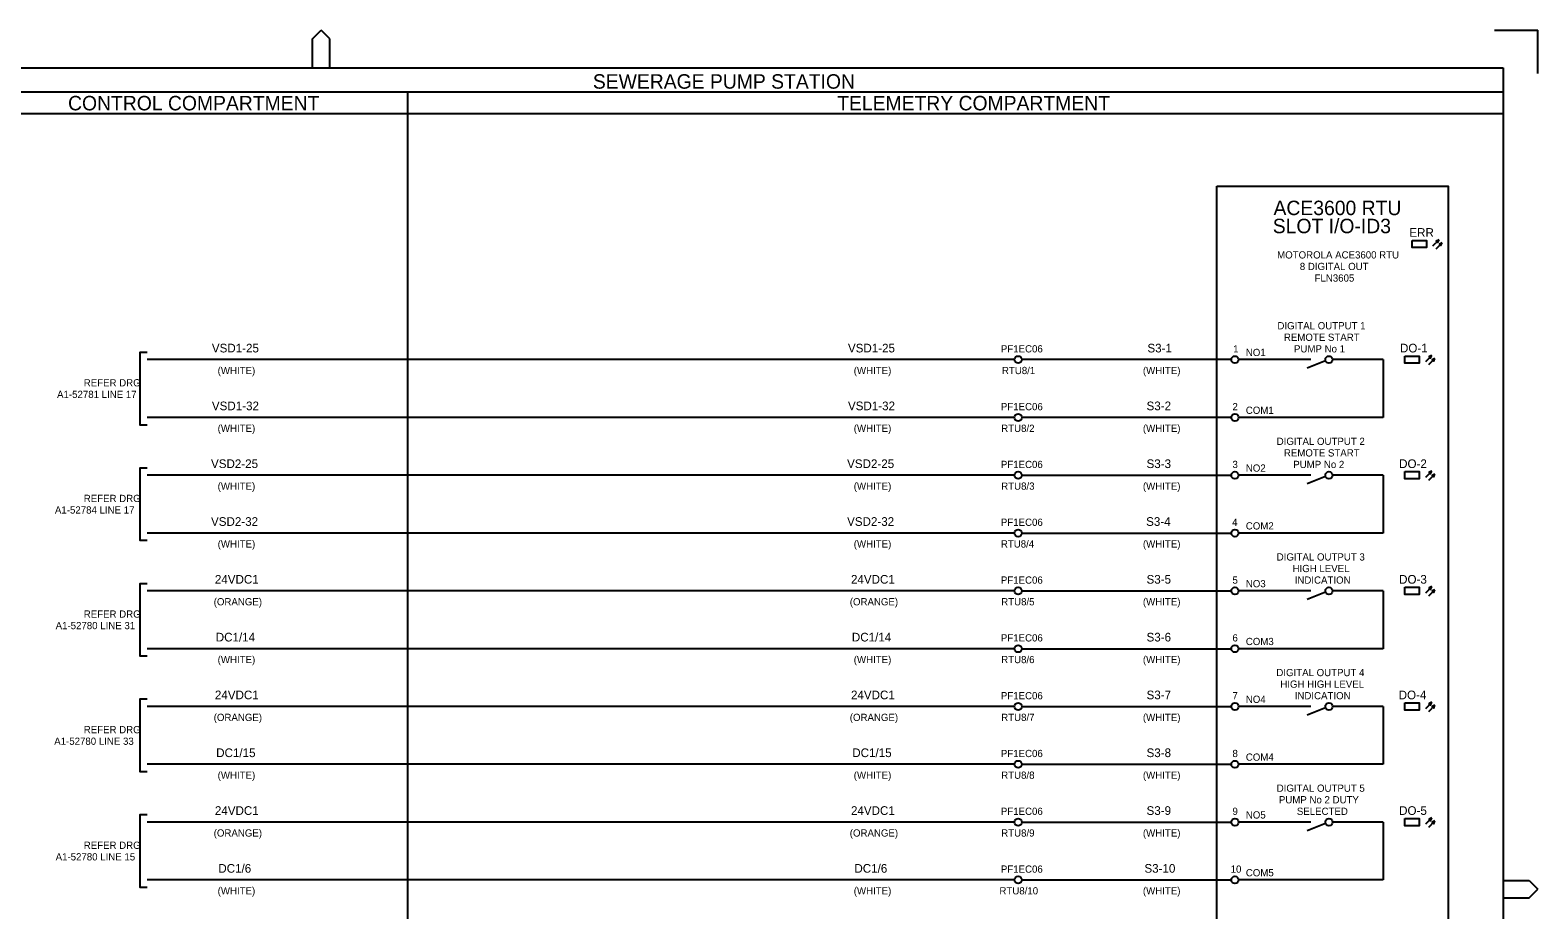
# Model space of a CAD drawing. Extents: x 0 to 841, y 0 to 594.
# Drawn here: x 320 to 841, y 290 to 594 of the extents above; entities that cross this region are included whole.
import ezdxf

# ---------------------------------------------------------------- set-up
doc = ezdxf.new("R2010")
doc.units = 0
for name, color, linetype in [('A1BORDER', 7, 'Continuous'), ('Level 1', 7, 'Continuous'), ('Level 10', 7, 'Continuous')]:
    doc.layers.add(name, color=color, linetype=linetype)

msp = doc.modelspace()

# ---------------------------------------------------------------- linework, layer by layer
at = {"layer": 'A1BORDER'}
for p, q in [((417.19, 591), (420.19, 594)), ((417.19, 581), (417.19, 591)), ((423.19, 591), (420.19, 594)), ((423.19, 581), (423.19, 591)), ((826, 594), (841, 594)), ((841, 579), (841, 594)), ((28, 581), (829, 581)), ((829, 581), (829, 15)), ((829, 299.76), (838, 299.76)), ((838, 299.76), (841, 296.76)), ((829, 293.76), (838, 293.76)), ((838, 293.76), (841, 296.76))]:
    msp.add_line(p, q, dxfattribs=at)
at = {"layer": 'Level 1'}
for p, q in [((829, 572.5), (160, 572.5)), ((450, 572.5), (450, 57)), ((829, 565), (160, 565)), ((660, 480), (360, 480)), ((735, 480), (662.5, 480)), ((760, 480), (737.5, 480)), ((762.5, 480), (760, 480)), ((787.5, 480), (770, 480)), ((787.5, 480), (787.5, 460)), ((660, 460), (360, 460)), ((735, 460), (662.5, 460)), ((787.5, 460), (737.5, 460)), ((660, 440), (360, 440)), ((662.5, 440), (735, 440)), ((760, 440), (737.5, 440)), ((762.5, 440), (760, 440)), ((787.5, 440), (770, 440)), ((787.5, 440), (787.5, 420)), ((660, 420), (360, 420)), ((662.5, 420), (735, 420)), ((787.5, 420), (737.5, 420)), ((660, 400), (360, 400)), ((662.5, 400), (735, 400)), ((760, 400), (737.5, 400)), ((762.5, 400), (760, 400)), ((787.5, 400), (770, 400)), ((787.5, 400), (787.5, 380)), ((660, 380), (360, 380)), ((662.5, 380), (735, 380)), ((787.5, 380), (737.5, 380)), ((660, 360), (360, 360)), ((662.5, 360), (735, 360)), ((760, 360), (737.5, 360)), ((762.5, 360), (760, 360)), ((787.5, 360), (770, 360)), ((787.5, 360), (787.5, 340)), ((660, 340), (360, 340)), ((662.5, 340), (735, 340)), ((787.5, 340), (737.5, 340)), ((660, 320), (360, 320)), ((662.5, 320), (735, 320)), ((760, 320), (737.5, 320)), ((762.5, 320), (760, 320)), ((787.5, 320), (770, 320)), ((787.5, 320), (787.5, 300)), ((660, 300), (360, 300)), ((662.5, 300), (735, 300)), ((787.5, 300), (737.5, 300))]:
    msp.add_line(p, q, dxfattribs=at)
for points in [[(730, 540), (810, 540), (810, 80), (730, 80)], [(797.5, 521.25), (802.5, 521.25), (802.5, 518.75), (797.5, 518.75)], [(795, 481.25), (800, 481.25), (800, 478.75), (795, 478.75)], [(795, 441.25), (800, 441.25), (800, 438.75), (795, 438.75)], [(795, 401.25), (800, 401.25), (800, 398.75), (795, 398.75)], [(795, 361.25), (800, 361.25), (800, 358.75), (795, 358.75)], [(795, 321.25), (800, 321.25), (800, 318.75), (795, 318.75)]]:
    msp.add_lwpolyline(points, close=True, dxfattribs=at)
for points in [[(360, 482.5), (357.5, 482.5), (357.5, 457.5), (360, 457.5)], [(360, 442.5), (357.5, 442.5), (357.5, 417.5), (360, 417.5)], [(360, 402.5), (357.5, 402.5), (357.5, 377.5), (360, 377.5)], [(360, 362.5), (357.5, 362.5), (357.5, 337.5), (360, 337.5)], [(360, 322.5), (357.5, 322.5), (357.5, 297.5), (360, 297.5)]]:
    msp.add_lwpolyline(points, dxfattribs=at)
for centre in [(661.25, 480), (736.25, 480), (661.25, 460), (736.25, 460), (661.25, 440), (736.25, 440), (661.25, 420), (736.25, 420), (661.25, 400), (736.25, 400), (661.25, 380), (736.25, 380), (661.25, 360), (736.25, 360), (661.25, 340), (736.25, 340), (661.25, 320), (736.25, 320), (661.25, 300), (736.25, 300)]:
    msp.add_circle(centre, 1.25, dxfattribs=at)
at = {"layer": 'Level 10'}
for p, q in [((804.73, 519.36), (806.86, 521.48)), ((805.79, 518.29), (807.91, 520.42)), ((805.96, 521.08), (806.67, 521.08)), ((806, 520.92), (806.61, 520.92)), ((806.14, 520.77), (806.53, 520.77)), ((806.29, 521.23), (806.74, 521.23)), ((806.3, 520.62), (806.47, 520.62)), ((806.62, 521.38), (806.81, 521.38)), ((807.02, 520.01), (807.73, 520.01)), ((807.06, 519.87), (807.66, 519.87)), ((807.21, 519.72), (807.6, 519.72)), ((807.35, 520.16), (807.8, 520.16)), ((807.36, 519.57), (807.53, 519.57)), ((807.68, 520.32), (807.87, 520.32)), ((802.23, 479.36), (804.36, 481.48)), ((803.29, 478.3), (805.41, 480.42)), ((803.46, 481.07), (804.17, 481.07)), ((803.5, 480.93), (804.11, 480.93)), ((803.64, 480.78), (804.03, 480.78)), ((803.79, 481.23), (804.24, 481.23)), ((803.8, 480.62), (803.97, 480.62)), ((804.12, 481.38), (804.31, 481.38)), ((804.52, 480.01), (805.23, 480.01)), ((804.56, 479.87), (805.16, 479.87)), ((804.85, 480.17), (805.3, 480.17)), ((805.18, 480.31), (805.37, 480.31)), ((767.59, 479.54), (761.25, 477)), ((804.71, 479.72), (805.1, 479.72)), ((804.86, 479.56), (805.03, 479.56)), ((767.59, 439.54), (761.25, 437)), ((802.23, 439.36), (804.36, 441.48)), ((803.29, 438.3), (805.41, 440.42)), ((803.46, 441.07), (804.17, 441.07)), ((803.5, 440.93), (804.11, 440.93)), ((803.64, 440.78), (804.03, 440.78)), ((803.79, 441.23), (804.24, 441.23)), ((803.8, 440.62), (803.97, 440.62)), ((804.12, 441.38), (804.31, 441.38)), ((804.52, 440.01), (805.23, 440.01)), ((804.56, 439.87), (805.16, 439.87)), ((804.71, 439.72), (805.1, 439.72)), ((804.85, 440.17), (805.3, 440.17)), ((804.86, 439.56), (805.03, 439.56)), ((805.18, 440.31), (805.37, 440.31)), ((767.59, 399.54), (761.25, 397)), ((802.23, 399.36), (804.36, 401.48)), ((803.29, 398.3), (805.41, 400.42)), ((803.46, 401.07), (804.17, 401.07)), ((803.5, 400.93), (804.11, 400.93)), ((803.64, 400.78), (804.03, 400.78)), ((803.79, 401.23), (804.24, 401.23)), ((803.8, 400.62), (803.97, 400.62)), ((804.12, 401.38), (804.31, 401.38)), ((804.52, 400.01), (805.23, 400.01)), ((804.56, 399.87), (805.16, 399.87)), ((804.71, 399.72), (805.1, 399.72)), ((804.85, 400.17), (805.3, 400.17)), ((804.86, 399.56), (805.03, 399.56)), ((805.18, 400.31), (805.37, 400.31)), ((802.23, 359.36), (804.36, 361.48)), ((803.29, 358.3), (805.41, 360.42)), ((803.46, 361.07), (804.17, 361.07)), ((803.5, 360.93), (804.11, 360.93)), ((803.64, 360.78), (804.03, 360.78)), ((803.79, 361.23), (804.24, 361.23)), ((803.8, 360.62), (803.97, 360.62)), ((804.12, 361.38), (804.31, 361.38)), ((804.52, 360.01), (805.23, 360.01)), ((804.56, 359.87), (805.16, 359.87)), ((804.85, 360.17), (805.3, 360.17)), ((805.18, 360.31), (805.37, 360.31)), ((767.59, 359.54), (761.25, 357)), ((804.71, 359.72), (805.1, 359.72)), ((804.86, 359.56), (805.03, 359.56)), ((767.59, 319.54), (761.25, 317)), ((802.23, 319.36), (804.36, 321.48)), ((803.29, 318.3), (805.41, 320.42)), ((803.46, 321.07), (804.17, 321.07)), ((803.5, 320.93), (804.11, 320.93)), ((803.64, 320.78), (804.03, 320.78)), ((803.79, 321.23), (804.24, 321.23)), ((803.8, 320.62), (803.97, 320.62)), ((804.12, 321.38), (804.31, 321.38)), ((804.52, 320.01), (805.23, 320.01)), ((804.56, 319.87), (805.16, 319.87)), ((804.71, 319.72), (805.1, 319.72)), ((804.85, 320.17), (805.3, 320.17)), ((804.86, 319.56), (805.03, 319.56)), ((805.18, 320.31), (805.37, 320.31))]:
    msp.add_line(p, q, dxfattribs=at)
for points in [[(806.86, 521.48), (805.88, 521.04), (806.41, 520.5)], [(807.91, 520.42), (806.94, 519.98), (807.48, 519.45)], [(804.36, 481.48), (803.38, 481.04), (803.91, 480.5)], [(805.41, 480.42), (804.44, 479.98), (804.98, 479.44)], [(804.36, 441.48), (803.38, 441.04), (803.91, 440.5)], [(805.41, 440.42), (804.44, 439.98), (804.98, 439.44)], [(804.36, 401.48), (803.38, 401.04), (803.91, 400.5)], [(805.41, 400.42), (804.44, 399.98), (804.98, 399.44)], [(804.36, 361.48), (803.38, 361.04), (803.91, 360.5)], [(805.41, 360.42), (804.44, 359.98), (804.98, 359.44)], [(804.36, 321.48), (803.38, 321.04), (803.91, 320.5)], [(805.41, 320.42), (804.44, 319.98), (804.98, 319.44)]]:
    msp.add_lwpolyline(points, close=True, dxfattribs=at)
for centre in [(768.75, 480), (768.75, 440), (768.75, 400), (768.75, 360), (768.75, 320)]:
    msp.add_circle(centre, 1.25, dxfattribs=at)

# ---------------------------------------------------------------- texts
at = {"layer": 'Level 1'}
for s, height, p in [('SEWERAGE PUMP STATION', 5, (514.16, 573.75)), ('CONTROL COMPARTMENT', 5, (332.65, 566.25)), ('TELEMETRY COMPARTMENT', 5, (598.66, 566.25)), ('ACE3600 RTU', 5, (749.58, 530)), ('SLOT I/O-ID3', 5, (749.33, 523.75)), ('ERR', 3, (796.56, 522.5)), ('MOTOROLA ACE3600 RTU', 2.5, (750.83, 515)), ('8 DIGITAL OUT', 2.5, (758.67, 511)), ('FLN3605', 2.5, (763.77, 507)), ('DIGITAL OUTPUT 1', 2.5, (750.93, 490.5)), ('VSD1-25', 3, (382.38, 482.5)), ('VSD1-25', 3, (602.38, 482.5)), ('PF1EC06', 2.5, (655.28, 482.5)), ('S3-1', 3, (705.97, 482.5)), ('1', 2.5, (735.63, 482.5)), ('REMOTE START', 2.5, (753.17, 486.5)), ('PUMP No 1', 2.5, (756.66, 482.5)), ('DO-1', 3, (793.32, 482.5)), ('NO1', 2.5, (740, 481.25)), ('(WHITE)', 2.5, (384.39, 475)), ('(WHITE)', 2.5, (604.39, 475)), ('RTU8/1', 2.5, (655.65, 475)), ('(WHITE)', 2.5, (704.4, 475)), ('REFER DRG', 2.5, (338.07, 470.75)), ('A1-52781 LINE 17', 2.5, (328.85, 466.75)), ('VSD1-32', 3, (382.39, 462.5)), ('VSD1-32', 3, (602.39, 462.5)), ('PF1EC06', 2.5, (655.28, 462.5)), ('S3-2', 3, (705.66, 462.5)), ('2', 2.5, (735.38, 462.5)), ('COM1', 2.5, (740, 461.25)), ('(WHITE)', 2.5, (384.39, 455)), ('(WHITE)', 2.5, (604.39, 455)), ('RTU8/2', 2.5, (655.4, 455)), ('(WHITE)', 2.5, (704.4, 455)), ('DIGITAL OUTPUT 2', 2.5, (750.68, 450.5)), ('REMOTE START', 2.5, (753.17, 446.5)), ('VSD2-25', 3, (382.09, 442.5)), ('VSD2-25', 3, (602.09, 442.5)), ('PF1EC06', 2.5, (655.28, 442.5)), ('S3-3', 3, (705.66, 442.5)), ('3', 2.5, (735.38, 442.5)), ('NO2', 2.5, (740, 441.25)), ('PUMP No 2', 2.5, (756.41, 442.5)), ('DO-2', 3, (793.02, 442.5)), ('REFER DRG', 2.5, (338.07, 430.75)), ('(WHITE)', 2.5, (384.39, 435)), ('(WHITE)', 2.5, (604.39, 435)), ('RTU8/3', 2.5, (655.4, 435)), ('(WHITE)', 2.5, (704.4, 435)), ('A1-52784 LINE 17', 2.5, (328.11, 426.75)), ('VSD2-32', 3, (382.09, 422.5)), ('VSD2-32', 3, (602.09, 422.5)), ('PF1EC06', 2.5, (655.28, 422.5)), ('S3-4', 3, (705.52, 422.5)), ('4', 2.5, (735.25, 422.5)), ('COM2', 2.5, (740, 421.25)), ('(WHITE)', 2.5, (384.39, 415)), ('(WHITE)', 2.5, (604.39, 415)), ('RTU8/4', 2.5, (655.28, 415)), ('(WHITE)', 2.5, (704.4, 415)), ('DIGITAL OUTPUT 3', 2.5, (750.68, 410.5)), ('HIGH LEVEL', 2.5, (756.16, 406.5)), ('24VDC1', 3, (383.43, 402.5)), ('24VDC1', 3, (603.43, 402.5)), ('PF1EC06', 2.5, (655.28, 402.5)), ('S3-5', 3, (705.66, 402.5)), ('5', 2.5, (735.38, 402.5)), ('NO3', 2.5, (740, 401.25)), ('INDICATION', 2.5, (756.91, 402.5)), ('DO-3', 3, (793.02, 402.5)), ('(ORANGE)', 2.5, (383.02, 395)), ('(ORANGE)', 2.5, (603.02, 395)), ('RTU8/5', 2.5, (655.4, 395)), ('(WHITE)', 2.5, (704.4, 395)), ('REFER DRG', 2.5, (338.07, 390.75)), ('A1-52780 LINE 31', 2.5, (328.35, 386.75)), ('DC1/14', 3, (383.74, 382.5)), ('DC1/14', 3, (603.74, 382.5)), ('PF1EC06', 2.5, (655.28, 382.5)), ('S3-6', 3, (705.66, 382.5)), ('6', 2.5, (735.38, 382.5)), ('COM3', 2.5, (740, 381.25)), ('(WHITE)', 2.5, (384.39, 375)), ('(WHITE)', 2.5, (604.39, 375)), ('RTU8/6', 2.5, (655.4, 375)), ('(WHITE)', 2.5, (704.4, 375)), ('DIGITAL OUTPUT 4', 2.5, (750.56, 370.5)), ('24VDC1', 3, (383.43, 362.5)), ('24VDC1', 3, (603.43, 362.5)), ('PF1EC06', 2.5, (655.28, 362.5)), ('S3-7', 3, (705.66, 362.5)), ('HIGH HIGH LEVEL', 2.5, (751.93, 366.5)), ('INDICATION', 2.5, (756.91, 362.5)), ('DO-4', 3, (792.87, 362.5)), ('7', 2.5, (735.38, 362.5)), ('NO4', 2.5, (740, 361.25)), ('(ORANGE)', 2.5, (383.02, 355)), ('(ORANGE)', 2.5, (603.02, 355)), ('RTU8/7', 2.5, (655.4, 355)), ('(WHITE)', 2.5, (704.4, 355)), ('REFER DRG', 2.5, (338.07, 350.75)), ('A1-52780 LINE 33', 2.5, (327.86, 346.75)), ('DC1/15', 3, (383.88, 342.5)), ('DC1/15', 3, (603.88, 342.5)), ('PF1EC06', 2.5, (655.28, 342.5)), ('S3-8', 3, (705.66, 342.5)), ('8', 2.5, (735.38, 342.5)), ('COM4', 2.5, (740, 341.25)), ('(WHITE)', 2.5, (384.39, 335)), ('(WHITE)', 2.5, (604.39, 335)), ('RTU8/8', 2.5, (655.4, 335)), ('(WHITE)', 2.5, (704.4, 335)), ('DIGITAL OUTPUT 5', 2.5, (750.68, 330.5)), ('PUMP No 2 DUTY', 2.5, (751.43, 326.5)), ('24VDC1', 3, (383.43, 322.5)), ('24VDC1', 3, (603.43, 322.5)), ('PF1EC06', 2.5, (655.28, 322.5)), ('S3-9', 3, (705.66, 322.5)), ('9', 2.5, (735.38, 322.5)), ('NO5', 2.5, (740, 321.25)), ('SELECTED', 2.5, (757.65, 322.5)), ('DO-5', 3, (793.02, 322.5)), ('REFER DRG', 2.5, (338.07, 310.75)), ('(ORANGE)', 2.5, (383.02, 315)), ('(ORANGE)', 2.5, (603.02, 315)), ('RTU8/9', 2.5, (655.4, 315)), ('(WHITE)', 2.5, (704.4, 315)), ('A1-52780 LINE 15', 2.5, (328.35, 306.75)), ('DC1/6', 3, (384.62, 302.5)), ('DC1/6', 3, (604.62, 302.5)), ('PF1EC06', 2.5, (655.28, 302.5)), ('S3-10', 3, (704.93, 302.5)), ('10', 2.5, (734.75, 302.5)), ('COM5', 2.5, (740, 301.25)), ('(WHITE)', 2.5, (384.39, 295)), ('(WHITE)', 2.5, (604.39, 295)), ('RTU8/10', 2.5, (654.78, 295)), ('(WHITE)', 2.5, (704.4, 295))]:
    msp.add_text(s, height=height, dxfattribs=at).set_placement(p)

doc.saveas('drawing.dxf')
